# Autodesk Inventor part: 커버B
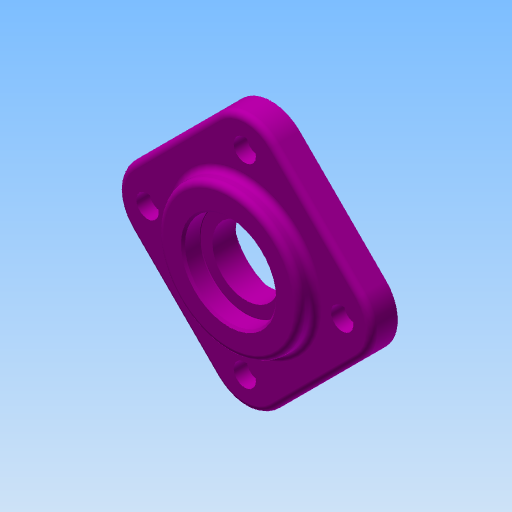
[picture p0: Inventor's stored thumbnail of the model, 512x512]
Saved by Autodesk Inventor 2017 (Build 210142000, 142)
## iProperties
Created: 2013-01
Part Number: 커버B
Document SubType Name: Modeling
Density: 1 g/cm^3
Material: 알루미늄 6061
Designer: mdu
Appearance: 자홍색
Author: mdu
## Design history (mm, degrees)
sketch "스케치1"
  geometry: L1 (56.569, -14.142)-(14.142, -56.569) reference; L2 (-14.142, -56.569)-(-56.569, -14.142) reference; L3 (-56.569, 14.142)-(-14.142, 56.569) reference; L4 (14.142, 56.569)-(56.569, 14.142) reference; C1 r 31 at (0, 0) reference; A1 r 20 centre (0, -42.426) between (-14.142, -56.569) and (14.142, -56.569) reference; A2 r 20 centre (-42.426, 0) between (-56.569, 14.142) and (-56.569, -14.142) reference; A3 r 20 centre (0, 42.426) between (14.142, 56.569) and (-14.142, 56.569) reference; A4 r 20 centre (42.426, 0) between (56.569, -14.142) and (56.569, 14.142) reference; 1 further point
extrude "돌출1" new body sketch "스케치1" distance "d0" = 13; taper "d1" = 0 deg
sketch "스케치2"
  geometry: C1 r 35 at (0, 0); 1 further point
  constraints: 1 centre point, 1 coincident
  dimensions: "d2" = 70 diameter of C1
extrude "돌출2" join sketch "스케치2" distance "d3" = 8; taper "d4" = 0 deg
fillet "모깎기1" dims "d5" = 3
sketch "스케치3"
  geometry: C1 r 2.458 at (0, 48) reference; 1 further point
hole "구멍1" sketch "스케치3" at (0, 48) diameter "d6" = 6.6; stored, may be unused: countersink angle "d10" = 90 deg, drill point angle "d12" = 118 deg; dims "d7" = 6, "d8" = 11, "d9" = 6.5, "d11" = 8
hole "구멍2" diameter "d18" = 33; stored, may be unused: countersink angle "d22" = 90 deg, drill point angle "d24" = 118 deg; dims "d19" = 6, "d20" = 45, "d21" = 8.5, "d23" = 8, "d41" = 10, "d42" = 10
sketch "스케치4"
  geometry: C1 r 31 at (0, 0) reference; 1 further point
extrude "돌출3" join sketch "스케치4" distance "d25" = 6; taper "d26" = 0 deg
hole "구멍3" diameter "d29" = 50; stored, may be unused: countersink angle "d33" = 90 deg, drill point angle "d35" = 0 deg; dims "d27" = 10, "d28" = 10, "d30" = 6, "d31" = 42, "d32" = 8.5, "d34" = 7
fillet "모깎기2" dims "d36" = 3, "d37" = 0.4
chamfer "모따기1" distance "d38" = 1; stored, may be unused: second distance "d39" = 2, angle "d40" = 45 deg
node "솔리드1"
pattern_circular "원형 패턴1" dims angle "d14" = 360 deg
node "참조1"
node "참조2"
node "참조3"
node "참조4"
node "참조5"
node "참조6"
node "참조7"
node "참조8"
node "참조9"
node "참조10"
node "참조11"
